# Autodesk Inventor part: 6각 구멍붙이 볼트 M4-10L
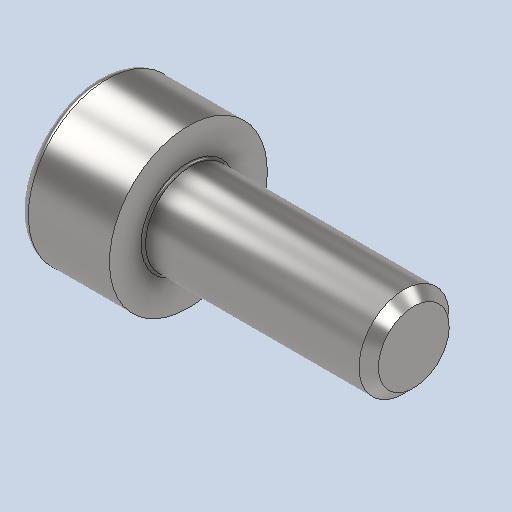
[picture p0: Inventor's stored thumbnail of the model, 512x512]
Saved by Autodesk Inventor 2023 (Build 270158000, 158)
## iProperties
Created: 2025-04
Part Number: 6각 구멍붙이 볼트 M4-10L
Material: 강철, 연강
Description: 6각머리 태핑 나사
Document SubType Name: Modeling
Designer: Admin
Mass: 2.0371 g
Surface Area: 3.0572 cm^2
Volume: 0.259174 cm^3
Density: 7.86 g/cm^3
Appearance: 기본값
Author: jhkim
Revision Number: 1
Sending System: Autodesk Inventor 2026
Preprocessor: ST-DEVELOPER v20.1
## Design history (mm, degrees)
feature "Solid1"
node "솔리드1"
